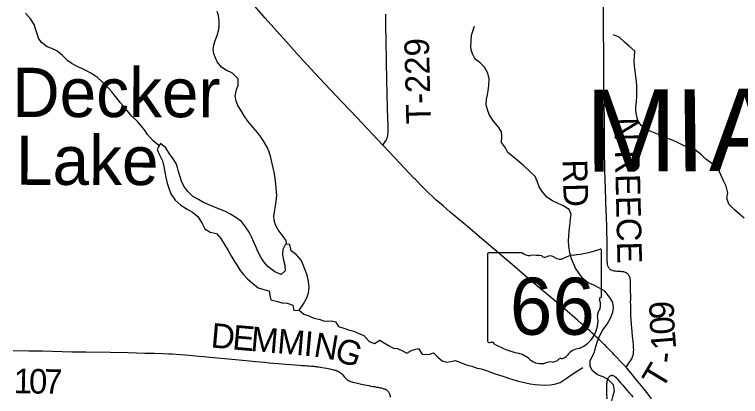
# Model space of a CAD drawing. Extents: x -87 to 2145, y -2128 to 440.
# Drawn here: x -43.667 to -41.988, y -693.004 to -692.122 of the extents above; entities that cross this region are included whole.
import ezdxf

# ---------------------------------------------------------------- set-up
doc = ezdxf.new("R2010")
doc.units = 0
for name, color, linetype in [('GM_X_County_Text', 7, 'Continuous'), ('GM_X_Minor_Lake', 7, 'Continuous'), ('GM_X_Minor_Lake_Text', 7, 'Continuous'), ('GM_X_Minor_River', 7, 'Continuous'), ('GM_X_State_Location', 7, 'Continuous'), ('GM_X_State_Route', 7, 'Continuous'), ('GM_X_State_Shield', 7, 'Continuous'), ('GM_X_Township_Road', 7, 'Continuous'), ('GM_X_Township_Road_Text', 7, 'Continuous')]:
    doc.layers.add(name, color=color, linetype=linetype)

msp = doc.modelspace()

# ---------------------------------------------------------------- linework, layer by layer
at = {"layer": 'GM_X_Minor_Lake'}
for points in [[(-43.2878, -692.485), (-43.2899, -692.4754), (-43.2935, -692.4659), (-43.2998, -692.4554), (-43.3083, -692.4435), (-43.3175, -692.4303), (-43.3298, -692.4201), (-43.337, -692.4336), (-43.3316, -692.4463), (-43.325, -692.4602), (-43.3215, -692.4728), (-43.3195, -692.4858), (-43.3171, -692.4987), (-43.3143, -692.5114), (-43.3097, -692.5251), (-43.3053, -692.5359), (-43.2954, -692.5506), (-43.2823, -692.5623), (-43.2677, -692.5718), (-43.2556, -692.5785), (-43.2429, -692.5887), (-43.233, -692.6045), (-43.2271, -692.6172), (-43.2144, -692.6251), (-43.2003, -692.6281), (-43.1899, -692.6394), (-43.1818, -692.6536), (-43.1726, -692.6671), (-43.1653, -692.6814), (-43.1583, -692.6926), (-43.1524, -692.7022), (-43.1454, -692.713), (-43.1373, -692.7227), (-43.128, -692.7324), (-43.116, -692.7437), (-43.1037, -692.7532), (-43.0908, -692.7576), (-43.0779, -692.7602), (-43.077, -692.7709), (-43.0746, -692.7808), (-43.0617, -692.7842), (-43.0481, -692.7879), (-43.0366, -692.7886), (-43.0238, -692.7938), (-43.021, -692.8057), (-43.0088, -692.8048)], [(-43.0088, -692.8048), (-43.0065, -692.8022), (-42.999, -692.7903), (-42.9922, -692.7783), (-42.9874, -692.7655), (-42.9859, -692.7522), (-42.9872, -692.7385), (-42.9903, -692.724), (-42.9939, -692.7144), (-42.9997, -692.7006), (-43.0044, -692.6898), (-43.0152, -692.6774), (-43.0275, -692.668), (-43.0302, -692.6535), (-43.0401, -692.6529), (-43.0465, -692.6649), (-43.0471, -692.6774), (-43.0447, -692.6892), (-43.0416, -692.7011), (-43.0411, -692.714), (-43.0508, -692.7229), (-43.0651, -692.7165), (-43.0801, -692.7051), (-43.0902, -692.6931), (-43.0972, -692.6827), (-43.1041, -692.6696), (-43.1092, -692.6577), (-43.1135, -692.6477), (-43.1194, -692.6354), (-43.1245, -692.625), (-43.1326, -692.6123), (-43.1422, -692.6002), (-43.1553, -692.5908), (-43.1692, -692.5821), (-43.179, -692.5769), (-43.193, -692.572), (-43.2058, -692.5664), (-43.219, -692.5611), (-43.2319, -692.5555), (-43.2416, -692.5496), (-43.2544, -692.5421), (-43.2664, -692.5311), (-43.2756, -692.5187), (-43.2807, -692.5068), (-43.2843, -692.4972), (-43.2878, -692.485), (-43.2899, -692.4754), (-43.2935, -692.4659), (-43.2998, -692.4554), (-43.3083, -692.4435), (-43.3175, -692.4303), (-43.3298, -692.4201), (-43.337, -692.4336), (-43.3316, -692.4463), (-43.325, -692.4602), (-43.3215, -692.4728), (-43.3195, -692.4858), (-43.3171, -692.4987), (-43.3143, -692.5114), (-43.3097, -692.5251), (-43.3053, -692.5359), (-43.2954, -692.5506), (-43.2823, -692.5623), (-43.2677, -692.5718), (-43.2556, -692.5785), (-43.2429, -692.5887), (-43.233, -692.6045), (-43.2271, -692.6172), (-43.2144, -692.6251), (-43.2003, -692.6281), (-43.1899, -692.6394), (-43.1818, -692.6536), (-43.1726, -692.6671), (-43.1653, -692.6814), (-43.1583, -692.6926), (-43.1524, -692.7022), (-43.1454, -692.713), (-43.1373, -692.7227), (-43.128, -692.7324), (-43.116, -692.7437), (-43.1037, -692.7532), (-43.0908, -692.7576), (-43.0779, -692.7602), (-43.077, -692.7709), (-43.0746, -692.7808), (-43.0617, -692.7842), (-43.0481, -692.7879), (-43.0366, -692.7886), (-43.0238, -692.7938), (-43.021, -692.8057), (-43.0088, -692.8048)], [(-43.0088, -692.8048), (-43.0065, -692.8022), (-42.999, -692.7903), (-42.9922, -692.7783), (-42.9874, -692.7655), (-42.9859, -692.7522), (-42.9872, -692.7385), (-42.9903, -692.724), (-42.9939, -692.7144), (-42.9997, -692.7006), (-43.0044, -692.6898), (-43.0152, -692.6774), (-43.0275, -692.668), (-43.0302, -692.6535), (-43.0401, -692.6529), (-43.0465, -692.6649), (-43.0471, -692.6774), (-43.0447, -692.6892), (-43.0416, -692.7011), (-43.0411, -692.714), (-43.0508, -692.7229), (-43.0651, -692.7165), (-43.0801, -692.7051), (-43.0902, -692.6931), (-43.0972, -692.6827), (-43.1041, -692.6696), (-43.1092, -692.6577), (-43.1135, -692.6477), (-43.1194, -692.6354), (-43.1245, -692.625), (-43.1326, -692.6123), (-43.1422, -692.6002), (-43.1553, -692.5908), (-43.1692, -692.5821), (-43.179, -692.5769), (-43.193, -692.572), (-43.2058, -692.5664), (-43.219, -692.5611), (-43.2319, -692.5555), (-43.2416, -692.5496), (-43.2544, -692.5421), (-43.2664, -692.5311), (-43.2756, -692.5187), (-43.2807, -692.5068), (-43.2843, -692.4972), (-43.2878, -692.485)]]:
    msp.add_lwpolyline(points, dxfattribs=at)
at = {"layer": 'GM_X_Minor_River'}
for points in [[(-43.0376, -692.653), (-43.0392, -692.6441), (-43.0484, -692.6321), (-43.0577, -692.6194), (-43.0639, -692.6078), (-43.0667, -692.5971), (-43.0673, -692.5876), (-43.0655, -692.5778), (-43.0633, -692.5641), (-43.0619, -692.5531), (-43.0605, -692.5402), (-43.0617, -692.5235), (-43.0626, -692.514), (-43.0646, -692.4998), (-43.0659, -692.4903), (-43.069, -692.4758), (-43.0715, -692.4662), (-43.0746, -692.4521), (-43.0781, -692.4394), (-43.0817, -692.4298), (-43.0905, -692.4156), (-43.0983, -692.404), (-43.1053, -692.3943), (-43.1153, -692.383), (-43.1272, -692.3687), (-43.1357, -692.3563), (-43.1438, -692.3432), (-43.1504, -692.3323), (-43.1544, -692.3212), (-43.1568, -692.3109), (-43.1534, -692.2954), (-43.1498, -692.2856), (-43.1498, -692.2703), (-43.1629, -692.2575), (-43.1779, -692.2503), (-43.1885, -692.2436), (-43.1988, -692.2311), (-43.2064, -692.2127), (-43.2074, -692.202), (-43.206, -692.1925), (-43.2027, -692.1816), (-43.1983, -692.1703), (-43.1949, -692.1563), (-43.1936, -692.1464), (-43.1937, -692.1365), (-43.1954, -692.1246), (-43.1986, -692.1147)], [(-43.3326, -692.4254), (-43.3465, -692.4137), (-43.3595, -692.3989), (-43.3665, -692.3885), (-43.3739, -692.3788), (-43.3828, -692.3691), (-43.3962, -692.3562), (-43.4103, -692.3391), (-43.4222, -692.3263), (-43.4337, -692.3116), (-43.4422, -692.3007), (-43.4512, -692.2906), (-43.4642, -692.2774), (-43.4754, -692.2672), (-43.4893, -692.2582), (-43.5006, -692.2518), (-43.5111, -692.2466), (-43.5225, -692.2418), (-43.5338, -692.2358), (-43.5439, -692.2291), (-43.5562, -692.2163), (-43.5693, -692.2061), (-43.5806, -692.2008), (-43.5912, -692.1968), (-43.6047, -692.1866), (-43.6117, -692.1765), (-43.6149, -692.1669), (-43.6185, -692.1551), (-43.6217, -692.1451), (-43.6301, -692.132), (-43.6413, -692.1188)], [(-42.6019, -692.2252), (-42.6073, -692.2147), (-42.6113, -692.204), (-42.6122, -692.1944), (-42.6112, -692.1842), (-42.6102, -692.1697), (-42.6061, -692.158), (-42.6036, -692.1485)], [(-42.2328, -692.2069), (-42.2458, -692.1947), (-42.2563, -692.1861), (-42.2686, -692.1744), (-42.2818, -692.1688)], [(-41.9799, -692.5927), (-41.9908, -692.5833), (-42.0024, -692.5731), (-42.015, -692.5599), (-42.0201, -692.5465), (-42.0175, -692.5343), (-42.0217, -692.5186), (-42.0276, -692.5063), (-42.033, -692.4936), (-42.0392, -692.4798), (-42.0545, -692.4665), (-42.0687, -692.4563), (-42.0788, -692.4465), (-42.0923, -692.4352), (-42.107, -692.4299), (-42.1198, -692.4243), (-42.1323, -692.4183), (-42.1443, -692.4127), (-42.1564, -692.4086), (-42.1674, -692.4034), (-42.1779, -692.3993), (-42.193, -692.3933), (-42.2055, -692.3877), (-42.2182, -692.3782), (-42.2256, -692.367), (-42.2287, -692.3536), (-42.23, -692.3437), (-42.2302, -692.3342), (-42.2289, -692.3239), (-42.2278, -692.3102), (-42.2276, -692.3003), (-42.228, -692.287), (-42.229, -692.2763), (-42.2306, -692.2652), (-42.2315, -692.253), (-42.2331, -692.2411), (-42.234, -692.2282), (-42.2334, -692.2187), (-42.2328, -692.2069)], [(-42.2859, -693.0148), (-42.2826, -693.0019), (-42.2793, -692.9917), (-42.2817, -692.9776), (-42.2936, -692.9659), (-42.306, -692.9588), (-42.3189, -692.9547), (-42.3312, -692.9441), (-42.3359, -692.9342), (-42.3357, -692.922), (-42.3316, -692.9122), (-42.3257, -692.9021), (-42.3228, -692.8888), (-42.3191, -692.8768), (-42.3142, -692.8651), (-42.3063, -692.8508), (-42.2965, -692.837), (-42.2889, -692.8235), (-42.2837, -692.8095), (-42.2816, -692.8), (-42.2836, -692.7871), (-42.2902, -692.7755), (-42.3021, -692.7615), (-42.3126, -692.7548), (-42.3276, -692.7476), (-42.3405, -692.7416), (-42.3517, -692.733), (-42.3617, -692.7206), (-42.3698, -692.7078), (-42.3745, -692.6971), (-42.3789, -692.6863), (-42.3831, -692.6722), (-42.3851, -692.6573), (-42.3863, -692.6451), (-42.3853, -692.6329), (-42.3843, -692.6223), (-42.3829, -692.6094), (-42.381, -692.5938), (-42.3797, -692.5836), (-42.3847, -692.5724), (-42.3986, -692.5637), (-42.4118, -692.5577), (-42.4228, -692.5521), (-42.4359, -692.5442), (-42.4467, -692.531), (-42.4537, -692.5198), (-42.4587, -692.5068), (-42.4634, -692.4964), (-42.4754, -692.4843), (-42.4899, -692.471), (-42.5004, -692.4624), (-42.5139, -692.4507), (-42.5266, -692.4405), (-42.5313, -692.4301), (-42.5406, -692.4173), (-42.5402, -692.4029), (-42.5408, -692.3933), (-42.5474, -692.3833), (-42.5593, -692.3686), (-42.5685, -692.3543), (-42.5729, -692.3443), (-42.5764, -692.3305), (-42.5757, -692.3179), (-42.5732, -692.3077), (-42.5715, -692.2982), (-42.5704, -692.2857), (-42.5697, -692.2704), (-42.5725, -692.2574), (-42.5806, -692.2435), (-42.5914, -692.233), (-42.6019, -692.2252)], [(-43.0088, -692.8048), (-42.998, -692.8146), (-42.9866, -692.8179), (-42.9746, -692.8232), (-42.9605, -692.8265), (-42.9507, -692.8306), (-42.9351, -692.8294), (-42.9249, -692.832), (-42.9175, -692.8431), (-42.9054, -692.8469), (-42.8944, -692.8505), (-42.8823, -692.8539), (-42.8725, -692.8583), (-42.8593, -692.8639), (-42.847, -692.8775), (-42.8345, -692.882), (-42.8222, -692.8747), (-42.8026, -692.8866), (-42.791, -692.8926), (-42.7811, -692.8935), (-42.7698, -692.8991), (-42.76, -692.9043), (-42.7473, -692.8978), (-42.7331, -692.8932), (-42.7246, -692.9063), (-42.7086, -692.9071), (-42.6979, -692.9035), (-42.6878, -692.9133), (-42.6781, -692.9222), (-42.6679, -692.9248), (-42.6583, -692.9235), (-42.6484, -692.9214), (-42.6359, -692.9259), (-42.6223, -692.9316), (-42.6098, -692.9345), (-42.5973, -692.939), (-42.5879, -692.9407), (-42.5739, -692.9453), (-42.5637, -692.9489), (-42.5531, -692.953), (-42.5379, -692.9575), (-42.5251, -692.9624), (-42.5145, -692.9653), (-42.5013, -692.969), (-42.4846, -692.9728), (-42.4743, -692.975), (-42.4633, -692.9764), (-42.4519, -692.9778), (-42.4409, -692.9784), (-42.4279, -692.9776), (-42.4153, -692.9756), (-42.4053, -692.9721), (-42.3914, -692.9629), (-42.3783, -692.9537), (-42.3651, -692.9452), (-42.3528, -692.9372)]]:
    msp.add_lwpolyline(points, dxfattribs=at)
at = {"layer": 'GM_X_State_Route'}
for points in [[(-42.7408, -692.5027), (-42.7429, -692.5005), (-42.7875, -692.4531), (-42.8155, -692.4236), (-42.8394, -692.3983), (-42.8755, -692.3601), (-42.9093, -692.3242), (-42.9624, -692.2681), (-43.0091, -692.2181), (-43.0383, -692.1851), (-43.0605, -692.1602), (-43.0871, -692.1304), (-43.1159, -692.0974), (-43.1267, -692.085)], [(-42.3015, -692.8861), (-42.3037, -692.884), (-42.3103, -692.8776), (-42.3162, -692.872), (-42.3209, -692.8675), (-42.3259, -692.8629), (-42.3306, -692.8586), (-42.3359, -692.8538), (-42.342, -692.8483), (-42.3491, -692.8421), (-42.3572, -692.8349), (-42.3648, -692.8285), (-42.3712, -692.8229), (-42.3778, -692.8173), (-42.4045, -692.7946), (-42.4248, -692.7774), (-42.4464, -692.7593), (-42.486, -692.7257), (-42.5109, -692.7043), (-42.5765, -692.6486), (-42.6243, -692.6082), (-42.6469, -692.5891), (-42.6597, -692.5783), (-42.668, -692.5712), (-42.6752, -692.565), (-42.6844, -692.5571), (-42.6924, -692.55), (-42.7002, -692.5427), (-42.7088, -692.5346), (-42.7237, -692.5201), (-42.7408, -692.5027)], [(-42.1938, -693.0101), (-42.202, -692.9994), (-42.2142, -692.9836), (-42.2295, -692.9649), (-42.2388, -692.954), (-42.253, -692.9369), (-42.2662, -692.9227), (-42.2734, -692.9149), (-42.2793, -692.9088), (-42.2844, -692.9034), (-42.2913, -692.8964), (-42.2973, -692.8905), (-42.3015, -692.8861)]]:
    msp.add_lwpolyline(points, dxfattribs=at)
at = {"layer": 'GM_X_State_Shield'}
for p, q in [((-42.3094, -692.7721), (-42.3094, -692.6674)), ((-42.5731, -692.6758), (-42.5731, -692.8759)), ((-42.4932, -692.6724), (-42.5705, -692.6724)), ((-42.3094, -692.7721), (-42.3094, -692.7721))]:
    msp.add_line(p, q, dxfattribs=at)
for centre, radius, start, end in [((-42.4033, -692.3995), 0.2796, 275.8445, 288.9065), ((-42.3123, -692.667), 0.00294, 351.8621, 97.738), ((-42.57, -692.6754), 0.00305, 98.1301, 188.1301), ((-42.4749, -692.6491), 0.0296, 231.6195, 271.1119), ((-42.465, -692.7847), 0.1064, 80.4867, 94.9883), ((-42.4409, -692.6743), 0.00855, 219.7921, 297.1024), ((-42.4283, -692.6975), 0.0178, 54.4667, 119.1411), ((-42.4054, -692.6657), 0.0214, 233.8562, 294.8282), ((-42.3676, -692.7335), 0.0563, 97.3462, 120.7689), ((-42.3101, -692.7798), 0.00454, 107.944, 210.337), ((-42.339, -692.793), 0.0273, 340.033, 23.6496), ((-42.3125, -692.7725), 0.00314, 289.6038, 7.7341), ((-42.2989, -692.8159), 0.0198, 136.8065, 186.9296), ((-42.3876, -692.8292), 0.0699, 292.3089, 8.9858), ((-42.57, -692.8764), 0.00308, 171.9584, 258.3066), ((-42.5695, -692.8559), 0.0235, 267.339, 280.6039), ((-42.5647, -692.8875), 0.00848, 29.7484, 93.2717), ((-42.4577, -692.7077), 0.2019, 240.4129, 257.1985), ((-42.5179, -692.9658), 0.0632, 47.1842, 75.836), ((-42.3582, -692.9321), 0.0383, 94.4031, 142.5768), ((-42.4495, -692.8885), 0.0401, 230.7004, 286.2918), ((-42.4234, -692.9034), 0.0214, 268.777, 315.5493), ((-42.4041, -692.9228), 0.00601, 65.7517, 132.6484), ((-42.4067, -692.8953), 0.0226, 282.8732, 323.2771), ((-42.4264, -692.9576), 0.0329, 85.6951, 111.2099)]:
    msp.add_arc(centre, radius, start, end, dxfattribs=at)
at = {"layer": 'GM_X_Township_Road'}
for points in [[(-42.3008, -692.519), (-42.3011, -692.509), (-42.3025, -692.4413), (-42.3031, -692.3804), (-42.3039, -692.3114), (-42.3041, -692.2791), (-42.3042, -692.253), (-42.3042, -692.2338), (-42.3045, -692.2083), (-42.305, -692.1636), (-42.3051, -692.1425), (-42.3053, -692.1126), (-42.3059, -692.0874)], [(-42.8155, -692.4236), (-42.8121, -692.4191), (-42.8104, -692.4168), (-42.8089, -692.4145), (-42.8078, -692.4127), (-42.8068, -692.4107), (-42.8059, -692.4087), (-42.8051, -692.4067), (-42.8046, -692.4049), (-42.8041, -692.4028), (-42.8037, -692.4005), (-42.8035, -692.3983), (-42.8032, -692.3955), (-42.8031, -692.3918), (-42.8033, -692.3784), (-42.8043, -692.3409), (-42.8051, -692.3026), (-42.806, -692.2751), (-42.8077, -692.1826), (-42.8082, -692.1488), (-42.8087, -692.1214)], [(-42.253, -692.9369), (-42.2461, -692.9273), (-42.244, -692.9239), (-42.2426, -692.9217), (-42.2412, -692.9197), (-42.2398, -692.9172), (-42.2386, -692.9148), (-42.2377, -692.9129), (-42.237, -692.9109), (-42.2364, -692.9086), (-42.236, -692.9064), (-42.2357, -692.9042), (-42.2354, -692.9), (-42.2353, -692.8965), (-42.2354, -692.8916), (-42.2358, -692.8851), (-42.2365, -692.8773), (-42.2378, -692.8651), (-42.2391, -692.8542), (-42.2399, -692.8461), (-42.2404, -692.8383), (-42.241, -692.8269), (-42.2415, -692.8172), (-42.2418, -692.8055), (-42.2421, -692.7936), (-42.2423, -692.7861), (-42.2422, -692.7802), (-42.2424, -692.7518), (-42.2426, -692.7407), (-42.2428, -692.7357), (-42.2432, -692.7324), (-42.2435, -692.7305), (-42.2439, -692.7287), (-42.2446, -692.727), (-42.2454, -692.7254), (-42.2464, -692.7238), (-42.2477, -692.7223), (-42.2489, -692.7212), (-42.2502, -692.7201), (-42.2517, -692.7191), (-42.2531, -692.7184), (-42.2545, -692.7178), (-42.2563, -692.7172), (-42.2577, -692.7168), (-42.2598, -692.7164), (-42.2624, -692.7161), (-42.2647, -692.7158), (-42.2673, -692.7157), (-42.2702, -692.7155), (-42.2739, -692.7153), (-42.2774, -692.7149), (-42.2806, -692.7146), (-42.283, -692.7142), (-42.2853, -692.7135), (-42.2869, -692.7128), (-42.2885, -692.7119), (-42.2898, -692.7109), (-42.2912, -692.7096), (-42.2923, -692.7082), (-42.293, -692.7071), (-42.2938, -692.7057), (-42.2944, -692.7044), (-42.295, -692.7028), (-42.2955, -692.7007), (-42.2958, -692.6985), (-42.2961, -692.6958), (-42.2962, -692.6936), (-42.2962, -692.6909), (-42.2963, -692.6866), (-42.2963, -692.6562), (-42.2973, -692.6112), (-42.2981, -692.591), (-42.2997, -692.5562), (-42.3008, -692.519)], [(-43.6704, -692.8984), (-43.6337, -692.8988), (-43.6024, -692.8993), (-43.5343, -692.9009), (-43.5021, -692.9015), (-43.4462, -692.9024), (-43.4046, -692.9031), (-43.3657, -692.9041), (-43.3438, -692.9046), (-43.3237, -692.9052), (-43.3099, -692.9058), (-43.3027, -692.9061), (-43.2936, -692.9066), (-43.2829, -692.9074), (-43.2719, -692.9082), (-43.2554, -692.9097), (-43.2398, -692.9111), (-43.2289, -692.9122), (-43.215, -692.9134), (-43.1562, -692.9188), (-43.1235, -692.922), (-43.1095, -692.9233), (-43.0983, -692.9244), (-43.0879, -692.9254), (-43.0782, -692.9264), (-43.0683, -692.9273), (-43.0573, -692.9283), (-43.0401, -692.9297), (-43.0283, -692.9306), (-43.0185, -692.9314), (-43.0077, -692.9323), (-43.0024, -692.9327), (-42.9985, -692.9329), (-42.9948, -692.9332), (-42.9905, -692.9335), (-42.986, -692.9338), (-42.9812, -692.9342), (-42.9778, -692.9344), (-42.9742, -692.9347), (-42.9717, -692.935), (-42.969, -692.9353), (-42.9664, -692.9356), (-42.9633, -692.9361), (-42.9594, -692.9368), (-42.9553, -692.9375), (-42.9512, -692.9383), (-42.9459, -692.9392), (-42.9418, -692.94), (-42.9381, -692.9406), (-42.9346, -692.9413), (-42.9317, -692.942), (-42.9293, -692.9425), (-42.9266, -692.9433), (-42.9242, -692.944), (-42.9219, -692.9448), (-42.9197, -692.9457), (-42.9178, -692.9467), (-42.9159, -692.9479), (-42.9142, -692.9491), (-42.9122, -692.9508), (-42.9103, -692.9523), (-42.9089, -692.9537), (-42.9066, -692.9564), (-42.9046, -692.9587), (-42.9023, -692.9614), (-42.9, -692.9639), (-42.8984, -692.9651), (-42.8969, -692.9661), (-42.8951, -692.9672), (-42.8936, -692.968), (-42.8917, -692.9689), (-42.89, -692.9696), (-42.8873, -692.9704), (-42.8846, -692.9712), (-42.8768, -692.973), (-42.8709, -692.9744), (-42.865, -692.9757), (-42.8573, -692.9775), (-42.8523, -692.9785), (-42.848, -692.9794), (-42.8431, -692.9803), (-42.8388, -692.981), (-42.8346, -692.9817), (-42.83, -692.9826), (-42.8261, -692.9833), (-42.822, -692.9841), (-42.8193, -692.9847), (-42.8166, -692.9853), (-42.8148, -692.9858), (-42.813, -692.9864), (-42.811, -692.9871), (-42.8096, -692.9877), (-42.8083, -692.9885), (-42.807, -692.9892), (-42.8058, -692.9901), (-42.8047, -692.991), (-42.8035, -692.9922), (-42.8023, -692.9936), (-42.8013, -692.995), (-42.8005, -692.9964), (-42.7998, -692.998), (-42.7992, -692.9995), (-42.7988, -693.0014), (-42.7986, -693.0037), (-42.7986, -693.0061)], [(-42.2967, -693.0099), (-42.2971, -692.9994), (-42.2972, -692.9922), (-42.2973, -692.982), (-42.297, -692.9745), (-42.2966, -692.9722), (-42.2963, -692.9693), (-42.2959, -692.967), (-42.2954, -692.965), (-42.2948, -692.9629), (-42.2943, -692.9618), (-42.2936, -692.9606), (-42.2929, -692.9597), (-42.2922, -692.9587), (-42.2915, -692.9579), (-42.2906, -692.9571), (-42.2896, -692.9564), (-42.2884, -692.9559), (-42.2874, -692.9557), (-42.2864, -692.9555), (-42.2854, -692.9555), (-42.2845, -692.9556), (-42.2834, -692.9558), (-42.2823, -692.9561), (-42.2813, -692.9566), (-42.2801, -692.9574), (-42.2787, -692.9585), (-42.2768, -692.9601), (-42.2752, -692.9619), (-42.2729, -692.9644), (-42.2693, -692.9684), (-42.2646, -692.9738), (-42.2606, -692.9784), (-42.2576, -692.9819), (-42.251, -692.9895), (-42.2455, -692.9957), (-42.2423, -692.9993), (-42.2403, -693.0016), (-42.2384, -693.0035), (-42.2366, -693.0052)]]:
    msp.add_lwpolyline(points, dxfattribs=at)

# ---------------------------------------------------------------- texts
at = {"layer": 'GM_X_County_Text'}
for s, rotation, p in [('M', 0.1487, (-42.3466, -692.485)), ('I', 0.7177, (-42.1387, -692.4845)), ('A', 0.7624, (-42.0611, -692.4835))]:
    msp.add_text(s, height=0.1894, rotation=rotation, dxfattribs=at).set_placement(p)
at = {"layer": 'GM_X_Minor_Lake_Text'}
for s, rotation, p in [('Decker', 359.9103, (-43.6725, -692.3586)), ('Lake', 359.8875, (-43.6637, -692.5154))]:
    msp.add_text(s, height=0.11365, rotation=rotation, dxfattribs=at).set_placement(p)
at = {"layer": 'GM_X_State_Location'}
msp.add_text('66', height=0.000189, rotation=0, dxfattribs=at).set_placement((-42.4919, -692.8029))
for s in ['s', 'r']:
    msp.add_text(s, height=0.000189, dxfattribs=at).set_placement((-42.4442, -692.7892))
at = {"layer": 'GM_X_State_Shield'}
msp.add_text('66', height=0.13184, dxfattribs=at).set_placement((-42.5215, -692.8618))
at = {"layer": 'GM_X_Township_Road_Text'}
for s, height, rotation, p in [('T-229', 0.05682, 91.3956, (-42.7042, -692.3742)), ('N REECE', 0.05682, 271.3224, (-42.2804, -692.3602)), ('RD', 0.05682, 271.4572, (-42.3995, -692.4574)), ('9', 0.0568, 91.6238, (-42.1415, -692.8252)), ('0', 0.0568, 93.2125, (-42.1396, -692.8597)), ('D', 0.0568, 354.9959, (-43.2145, -692.891)), ('E', 0.0568, 354.9922, (-43.1647, -692.8954)), ('M', 0.0568, 354.9961, (-43.1224, -692.8991)), ('M', 0.0568, 354.9903, (-43.061, -692.9044)), ('I', 0.0568, 354.9038, (-42.9996, -692.9098)), ('N', 0.0568, 350.4077, (-42.9775, -692.9117)), ('G', 0.0568, 341.1757, (-42.9305, -692.9195)), ('1', 0.0568, 94.5901, (-42.1368, -692.8942)), ('-', 0.0568, 83.2313, (-42.1398, -692.9297)), ('T', 0.0568, 59.0936, (-42.17, -692.9906)), ('1', 0.0568, 358.6761, (-43.6693, -692.9966)), ('0', 0.0568, 359.1553, (-43.6338, -692.9975)), ('7', 0.0568, 359.2866, (-43.5986, -692.998))]:
    msp.add_text(s, height=height, rotation=rotation, dxfattribs=at).set_placement(p)

doc.saveas('drawing.dxf')
